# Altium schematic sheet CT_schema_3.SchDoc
size 294 x 169 mm
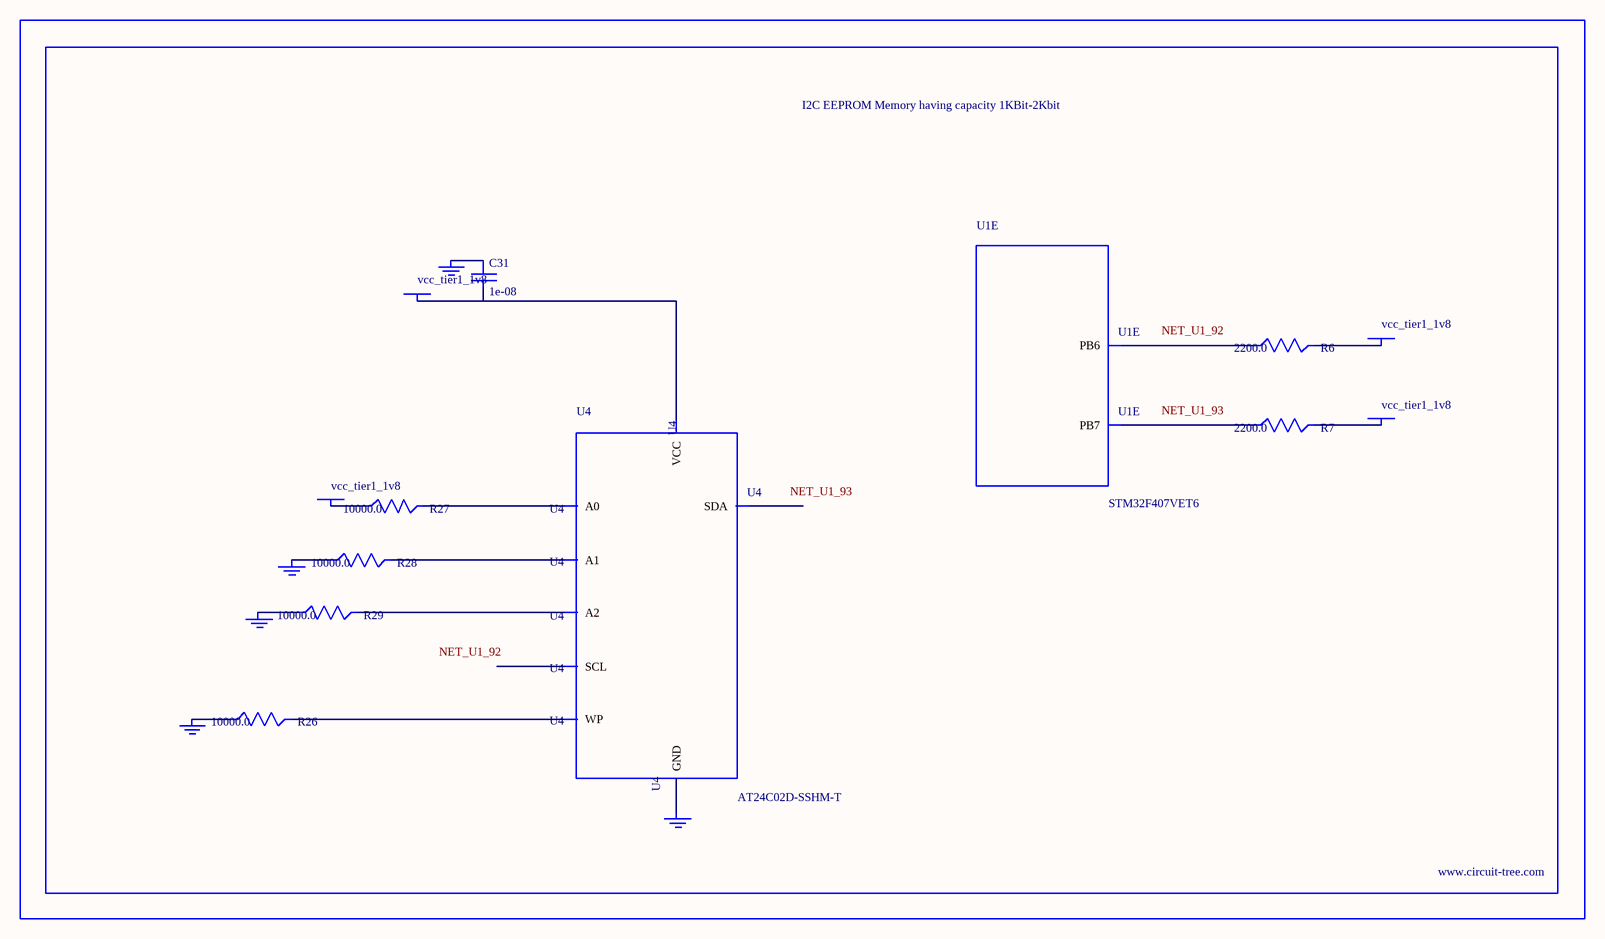
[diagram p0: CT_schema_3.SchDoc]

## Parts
BORDER2  (no value)
C31  1e-08  [C0402]
GND_INSTANCE_2_0  (no value)
GND_INSTANCE_2_1  (no value)
GND_INSTANCE_2_2  (no value)
GND_INSTANCE_2_3  (no value)
GND_INSTANCE_2_4  (no value)
POWER_INSTANCE_2_0  vcc_tier1_1v8
POWER_INSTANCE_2_1  vcc_tier1_1v8
POWER_INSTANCE_2_2  vcc_tier1_1v8
POWER_INSTANCE_2_3  vcc_tier1_1v8
R6  2200.0  [R0603]
R7  2200.0  [R0603]
R26  10000.0  [R0603]
R27  10000.0  [R0603]
R28  10000.0  [R0603]
R29  10000.0  [R0603]
U1  STM32F407VET6  [LQFP100]  (part E of 8)
U4  AT24C02D-SSHM-T  [AT24C02D]

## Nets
NetC31_1: C31.1 GND_INSTANCE_2_3.0(GND)
NetC31_2: C31.2 POWER_INSTANCE_2_1.0(PWR) U4.8(VCC)
NetGND_INSTANCE_2_0_0: GND_INSTANCE_2_0.0(GND) R28.1
NetGND_INSTANCE_2_1_0: GND_INSTANCE_2_1.0(GND) R29.1
NetGND_INSTANCE_2_2_0: GND_INSTANCE_2_2.0(GND) R26.1
NetGND_INSTANCE_2_4_0: GND_INSTANCE_2_4.0(GND) U4.4(GND)
NetPOWER_INSTANCE_2_0_0: POWER_INSTANCE_2_0.0(PWR) R27.1
NetPOWER_INSTANCE_2_2_0: POWER_INSTANCE_2_2.0(PWR) R6.2
NetPOWER_INSTANCE_2_3_0: POWER_INSTANCE_2_3.0(PWR) R7.2
NetR6_1: R6.1 U1.92(PB6)
NetR7_1: R7.1 U1.93(PB7)
NetR26_2: R26.2 U4.7(WP)
NetR27_2: R27.2 U4.1(A0)
NetR28_2: R28.2 U4.2(A1)
NetR29_2: R29.2 U4.3(A2)

Not connected (* = marked no-connect by the designer): U4 5(SDA) 6(SCL)

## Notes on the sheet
- Labels drawn without touching a wire or pin: NET_U1_92, NET_U1_93

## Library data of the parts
BORDER2 = BORDER_PAGE2
C31 = C0402C103K3RAC
GND_INSTANCE_2_0-GND_INSTANCE_2_4 = GND
POWER_INSTANCE_2_0-POWER_INSTANCE_2_3 = PWR
R6 R7 = RC0603JR-072K2L
R26-R29 = RC0603JR-0710KL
